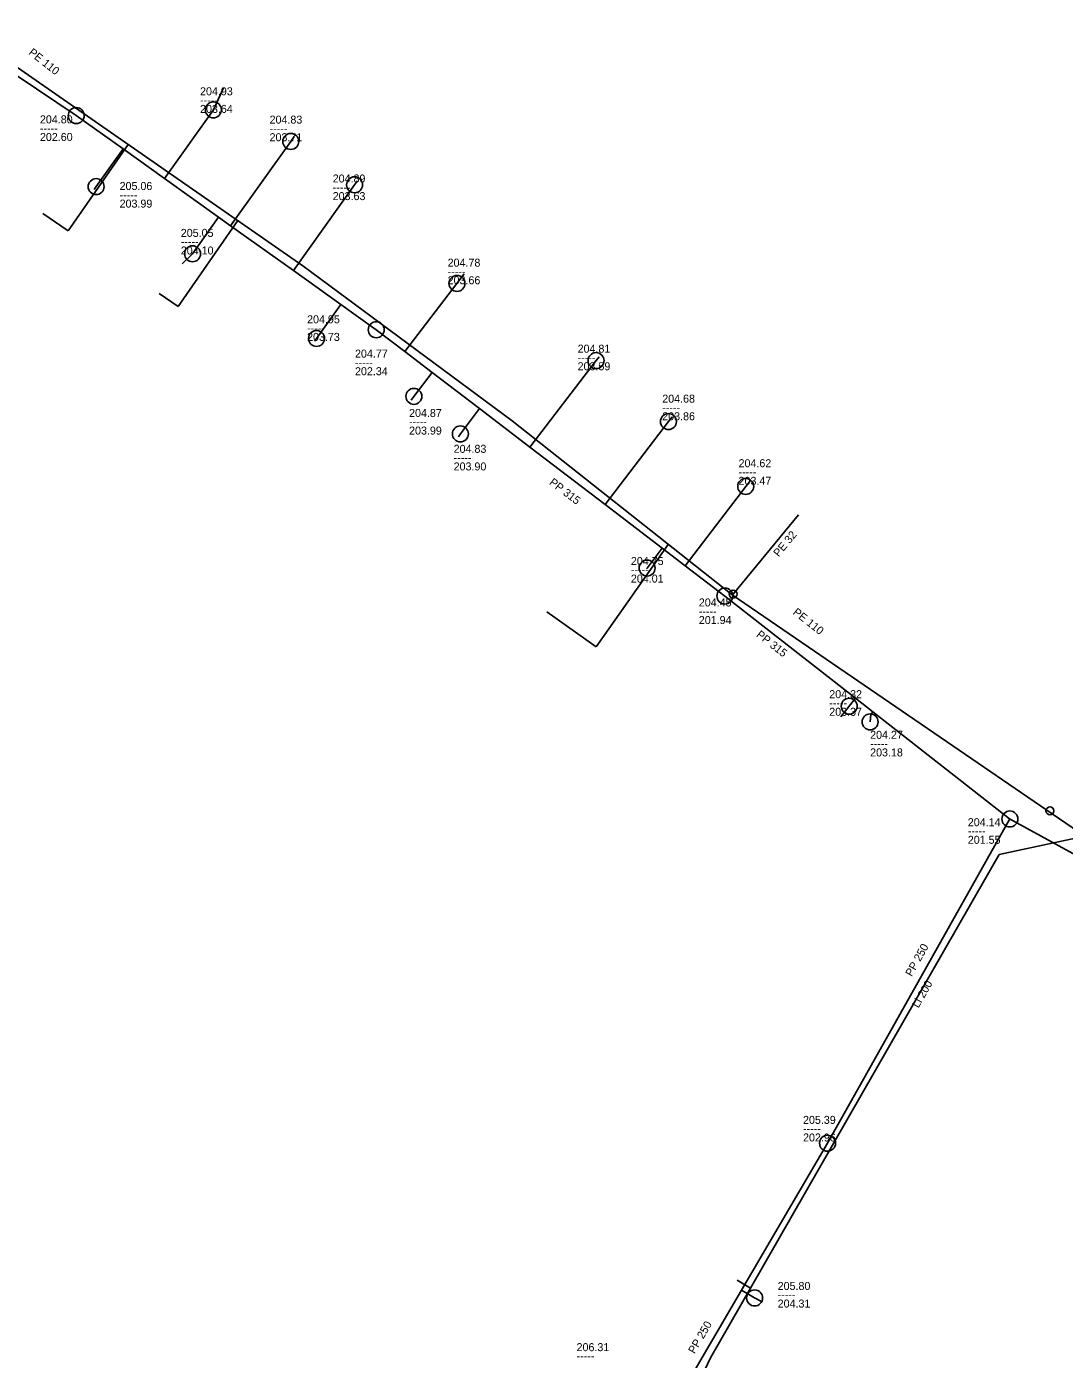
# Model space of a CAD drawing. Extents: x -695225 to -694112, y -1052622 to -1052029.
# Drawn here: x -694950.1 to -694820.4, y -1052495 to -1052328.4 of the extents above; entities that cross this region are included whole.
import ezdxf

# ---------------------------------------------------------------- set-up
doc = ezdxf.new("R2010")
doc.units = 0
doc.layers.add('Level 0', color=7, linetype='Continuous')

msp = doc.modelspace()

# ---------------------------------------------------------------- linework, layer by layer
at = {"layer": 'Level 0'}
for p, q in [((-694960.42, -1052328.4), (-694943.9, -1052339.52)), ((-694954.58, -1052331.21), (-694915.56, -1052358.3)), ((-694925.49, -1052336.06), (-694926.76, -1052338.8)), ((-694943.9, -1052339.52), (-694938.05, -1052343.69)), ((-694926.76, -1052338.8), (-694932.88, -1052347.38)), ((-694944.93, -1052353.94), (-694937.41, -1052343.13)), ((-694917.08, -1052342.75), (-694924.6, -1052353.28)), ((-694916.66, -1052342.15), (-694917.08, -1052342.75)), ((-694941.41, -1052348.4), (-694938.05, -1052343.69)), ((-694938.05, -1052343.69), (-694932.88, -1052347.38)), ((-694941.66, -1052348.75), (-694941.41, -1052348.4)), ((-694932.88, -1052347.38), (-694926.1, -1052352.22)), ((-694909.1, -1052348.17), (-694916.74, -1052358.89)), ((-694908.74, -1052347.67), (-694909.1, -1052348.17)), ((-694948.09, -1052351.75), (-694944.93, -1052353.94)), ((-694923.69, -1052352.65), (-694931.15, -1052363.39)), ((-694929.36, -1052356.79), (-694926.1, -1052352.22)), ((-694926.1, -1052352.22), (-694924.6, -1052353.28)), ((-694924.6, -1052353.28), (-694916.74, -1052358.89)), ((-694930.64, -1052358.03), (-694929.36, -1052356.79)), ((-694915.56, -1052358.3), (-694889.39, -1052377.67)), ((-694916.74, -1052358.89), (-694910.82, -1052363.11)), ((-694895.42, -1052359.28), (-694896.3, -1052360.49)), ((-694933.52, -1052361.76), (-694931.15, -1052363.39)), ((-694896.3, -1052360.49), (-694902.81, -1052369.01)), ((-694913.86, -1052367.37), (-694910.82, -1052363.11)), ((-694910.82, -1052363.11), (-694906.39, -1052366.28)), ((-694906.39, -1052366.28), (-694902.81, -1052369.02)), ((-694914.1, -1052367.72), (-694913.86, -1052367.37)), ((-694902.81, -1052369.02), (-694899.41, -1052371.61)), ((-694878.92, -1052370.15), (-694887.18, -1052380.95)), ((-694878.51, -1052369.66), (-694878.92, -1052370.15)), ((-694901.69, -1052374.61), (-694899.41, -1052371.61)), ((-694899.41, -1052371.61), (-694893.47, -1052376.14)), ((-694902.04, -1052375.1), (-694901.69, -1052374.61)), ((-694895.88, -1052379.3), (-694893.47, -1052376.14)), ((-694893.47, -1052376.14), (-694887.18, -1052380.95)), ((-694889.39, -1052377.67), (-694861.88, -1052399.44)), ((-694869.86, -1052377.77), (-694877.78, -1052388.13)), ((-694869.4, -1052377.19), (-694869.86, -1052377.77)), ((-694896.13, -1052379.66), (-694895.88, -1052379.3)), ((-694887.18, -1052380.95), (-694877.78, -1052388.13)), ((-694859.61, -1052385.15), (-694860.21, -1052385.87)), ((-694860.21, -1052385.87), (-694867.77, -1052395.78)), ((-694877.78, -1052388.13), (-694870.64, -1052393.59)), ((-694861.79, -1052399.32), (-694853.6, -1052389.42)), ((-694878.9, -1052405.91), (-694869.88, -1052393.11)), ((-694872.53, -1052396.07), (-694870.64, -1052393.59)), ((-694870.64, -1052393.59), (-694867.77, -1052395.78)), ((-694872.62, -1052396.18), (-694872.53, -1052396.07)), ((-694867.77, -1052395.78), (-694862.81, -1052399.57)), ((-694862.81, -1052399.57), (-694846.5, -1052412.35)), ((-694861.88, -1052399.44), (-694861.79, -1052399.32)), ((-694861.88, -1052399.44), (-694817.8, -1052429.59)), ((-694885.07, -1052401.56), (-694878.9, -1052405.91)), ((-694848.3, -1052414.68), (-694847.27, -1052413.34)), ((-694847.27, -1052413.34), (-694846.5, -1052412.35)), ((-694846.5, -1052412.35), (-694844.31, -1052414.06)), ((-694844.65, -1052415.3), (-694844.56, -1052414.37)), ((-694844.56, -1052414.37), (-694844.31, -1052414.06)), ((-694844.31, -1052414.06), (-694827.23, -1052427.44)), ((-694849.98, -1052467.97), (-694827.18, -1052427.44)), ((-694827.23, -1052427.44), (-694817.1, -1052432.95)), ((-694828.53, -1052431.86), (-694817.8, -1052429.59)), ((-694828.53, -1052431.86), (-694859.59, -1052486.07)), ((-694860.74, -1052486.34), (-694849.98, -1052467.97)), ((-694861.26, -1052485.09), (-694859.59, -1052486.07)), ((-694870.74, -1052503.4), (-694860.74, -1052486.34)), ((-694859.59, -1052486.07), (-694864.59, -1052494.8)), ((-694859.59, -1052486.07), (-694864.59, -1052494.8)), ((-694859.09, -1052487.31), (-694860.74, -1052486.34)), ((-694858.25, -1052487.74), (-694859.09, -1052487.31)), ((-694864.59, -1052494.8), (-694874.02, -1052514.21)), ((-694864.59, -1052494.8), (-694874.02, -1052514.21))]:
    msp.add_line(p, q, dxfattribs=at)
for centre, radius in [((-694943.9, -1052339.52), 1), ((-694926.76, -1052338.8), 1), ((-694917.08, -1052342.75), 1), ((-694941.41, -1052348.4), 1), ((-694909.1, -1052348.17), 1), ((-694929.36, -1052356.79), 1), ((-694896.3, -1052360.49), 1), ((-694913.86, -1052367.37), 1), ((-694906.39, -1052366.28), 1), ((-694878.92, -1052370.15), 1), ((-694901.69, -1052374.61), 1), ((-694869.86, -1052377.77), 1), ((-694895.88, -1052379.3), 1), ((-694860.21, -1052385.87), 1), ((-694872.53, -1052396.07), 1), ((-694862.81, -1052399.57), 1), ((-694861.79, -1052399.32), 0.5), ((-694847.27, -1052413.34), 1), ((-694844.65, -1052415.3), 1), ((-694827.18, -1052427.44), 1), ((-694822.17, -1052426.42), 0.5), ((-694849.98, -1052467.97), 1), ((-694859.09, -1052487.31), 1)]:
    msp.add_circle(centre, radius, dxfattribs=at)

# ---------------------------------------------------------------- texts
for s, rotation, p in [('PE 110', 321.644, (-694949.94, -1052331.79)), ('PP 315', 322.626, (-694884.84, -1052385.54)), ('PE 32', 50.4, (-694856.08, -1052394.75)), ('PE 110', 321.644, (-694854.39, -1052401.76)), ('PP 315', 322.017, (-694858.97, -1052404.57)), ('PP 250', 60.64, (-694839.45, -1052447.21)), ('Li 200', 60.189, (-694838.62, -1052451.14)), ('PP 250', 59.623, (-694866.6, -1052494.36))]:
    msp.add_text(s, height=1, rotation=rotation, dxfattribs=at).set_placement(p)
for s, p in [('204.93', (-694928.42, -1052336.98)), ('-----', (-694928.42, -1052338.08)), ('203.64', (-694928.42, -1052339.18)), ('204.80', (-694948.44, -1052340.49)), ('204.83', (-694919.73, -1052340.52)), ('-----', (-694948.44, -1052341.59)), ('202.60', (-694948.44, -1052342.69)), ('-----', (-694919.73, -1052341.62)), ('203.71', (-694919.73, -1052342.72)), ('204.89', (-694911.84, -1052347.88)), ('205.06', (-694938.48, -1052348.82)), ('-----', (-694911.84, -1052348.98)), ('-----', (-694938.48, -1052349.92)), ('203.99', (-694938.48, -1052351.02)), ('203.63', (-694911.84, -1052350.08)), ('205.05', (-694930.83, -1052354.68)), ('-----', (-694930.83, -1052355.78)), ('204.10', (-694930.83, -1052356.88)), ('204.78', (-694897.47, -1052358.4)), ('-----', (-694897.47, -1052359.5)), ('203.66', (-694897.47, -1052360.6)), ('204.95', (-694915.04, -1052365.48)), ('-----', (-694915.04, -1052366.58)), ('203.73', (-694915.04, -1052367.68)), ('204.81', (-694881.22, -1052369.15)), ('204.77', (-694909.05, -1052369.77)), ('-----', (-694881.22, -1052370.25)), ('-----', (-694909.05, -1052370.87)), ('202.34', (-694909.05, -1052371.97)), ('203.59', (-694881.22, -1052371.35)), ('204.68', (-694870.64, -1052375.4)), ('204.87', (-694902.29, -1052377.19)), ('-----', (-694870.64, -1052376.5)), ('203.86', (-694870.64, -1052377.6)), ('-----', (-694902.29, -1052378.29)), ('203.99', (-694902.29, -1052379.39)), ('204.83', (-694896.72, -1052381.67)), ('-----', (-694896.72, -1052382.77)), ('203.90', (-694896.72, -1052383.87)), ('204.62', (-694861.1, -1052383.47)), ('-----', (-694861.1, -1052384.57)), ('203.47', (-694861.1, -1052385.67)), ('204.75', (-694874.56, -1052395.69)), ('-----', (-694874.56, -1052396.79)), ('204.01', (-694874.56, -1052397.89)), ('204.45', (-694866.07, -1052400.87)), ('-----', (-694866.07, -1052401.97)), ('201.94', (-694866.07, -1052403.07)), ('204.32', (-694849.76, -1052412.34)), ('-----', (-694849.76, -1052413.44)), ('203.37', (-694849.76, -1052414.54)), ('204.27', (-694844.65, -1052417.42)), ('-----', (-694844.65, -1052418.52)), ('203.18', (-694844.65, -1052419.62)), ('204.14', (-694832.44, -1052428.34)), ('-----', (-694832.44, -1052429.44)), ('201.55', (-694832.44, -1052430.54)), ('205.39', (-694853.04, -1052465.55)), ('-----', (-694853.04, -1052466.65)), ('202.96', (-694853.04, -1052467.75)), ('205.80', (-694856.21, -1052486.31)), ('-----', (-694856.21, -1052487.41)), ('204.31', (-694856.21, -1052488.51)), ('206.31', (-694881.35, -1052493.96)), ('-----', (-694881.35, -1052495.06))]:
    msp.add_text(s, height=1, dxfattribs=at).set_placement(p)

doc.saveas('drawing.dxf')
